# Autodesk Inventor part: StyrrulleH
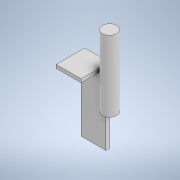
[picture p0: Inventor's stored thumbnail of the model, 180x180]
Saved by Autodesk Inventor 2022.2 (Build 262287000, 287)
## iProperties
Created: 2022-03
Part Number: StyrrulleH
Material: Generic
Document SubType Name: Modeling
Designer: cl
Density: 1 g/cm^3
Appearance: Default
Author: cl
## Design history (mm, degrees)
sketch "Sketch1"
  geometry: L1 (0, 0)-(0, -5); L2 (0, -5)-(105, -5); L3 (105, -5)-(105, 35); L4 (105, 35)-(100, 35); L5 (100, 35)-(100, 0); L6 (100, 0)-(0, 0)
  constraints: 12 end point, 5 perpendicular, 1 vertical
  dimensions: "d0" = 5 distance of L1.start L1.end; "d1" = 5 distance between parallel lines of L3 L5; "d2" = 105 distance of L1.end L2.end; "d3" = 40 distance of L2.end L3.end
extrude "Extrusion1" new body sketch "Sketch1" distance "d4" = 35; taper "d5" = 0 deg
sketch "Sketch2"
  geometry: L1 (0, 40)-(0, 0) reference; L2 (0, 0)-(35, 0) reference; L3 (35, 40)-(35, 0) reference; L4 (0, 40)-(35, 40) reference; C1 r 10 at (45, 30); 1 further point
  constraints: 2 tangent, 1 centre point
  dimensions: "d6" = 20 diameter of C1
extrude "Extrusion2" join sketch "Sketch2" distance "d7" = 50; taper "d9" = 0 deg; dims "d8" = 50, "d10" = 0
body "Solid1"
node "Projected Loop1"
